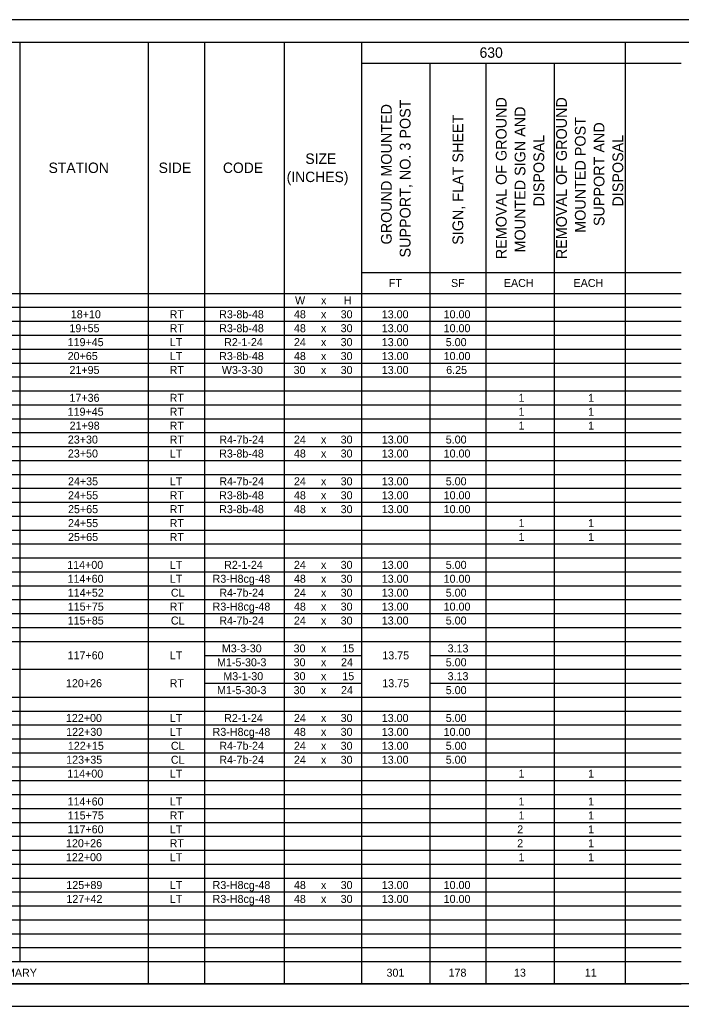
# Model space of a CAD drawing. Extents: x 10.3 to 44.3, y 3.4 to 25.4.
# Drawn here: x 18.06 to 32.81, y 3.4 to 25.4 of the extents above; entities that cross this region are included whole.
import ezdxf

# ---------------------------------------------------------------- set-up
doc = ezdxf.new("R2010")
doc.units = 0
for name, color, linetype in [('SH_Border', 7, 'Continuous'), ('SH_Cut_Line', 7, 'Continuous'), ('SH_Text', 7, 'Continuous')]:
    doc.layers.add(name, color=color, linetype=linetype)

msp = doc.modelspace()

# ---------------------------------------------------------------- linework, layer by layer
at = {"layer": 'SH_Border'}
msp.add_lwpolyline([(12.306, 24.905), (43.806, 24.905), (43.806, 3.905), (12.306, 3.905)], close=True, dxfattribs=at)
at = {"layer": 'SH_Cut_Line'}
msp.add_lwpolyline([(10.306, 3.405), (44.306, 3.405), (44.306, 25.405), (10.306, 25.405)], close=True, dxfattribs=at)
at = {"layer": 'SH_Text'}
for p, q in [((12.306, 24.905), (18.057, 24.905)), ((18.057, 24.905), (20.924, 24.905)), ((18.057, 24.905), (18.057, 19.767)), ((20.924, 24.905), (23.952, 24.905)), ((20.924, 24.905), (20.924, 19.767)), ((22.174, 24.905), (22.174, 19.767)), ((23.952, 24.905), (24.657, 24.905)), ((23.952, 24.905), (23.952, 19.767)), ((24.657, 24.905), (32.81, 24.905)), ((25.682, 24.905), (25.682, 19.767)), ((31.561, 24.905), (31.561, 19.767)), ((25.682, 24.439), (32.81, 24.439)), ((27.204, 24.439), (27.204, 19.767)), ((28.453, 24.439), (28.453, 19.767)), ((29.975, 24.439), (29.975, 19.767)), ((18.057, 19.767), (18.057, 11.851)), ((20.924, 19.767), (20.924, 11.851)), ((22.174, 19.767), (22.174, 11.851)), ((23.952, 19.767), (23.952, 11.851)), ((25.682, 19.767), (32.81, 19.767)), ((25.682, 19.767), (25.682, 11.851)), ((27.204, 19.767), (27.204, 11.851)), ((28.453, 19.767), (28.453, 11.851)), ((29.975, 19.767), (29.975, 11.851)), ((31.561, 19.767), (31.561, 11.851)), ((12.306, 19.301), (18.057, 19.301)), ((18.057, 19.301), (20.924, 19.301)), ((20.924, 19.301), (23.952, 19.301)), ((23.952, 19.301), (24.657, 19.301)), ((24.657, 19.301), (32.81, 19.301)), ((12.306, 18.991), (18.057, 18.991)), ((18.057, 18.991), (20.924, 18.991)), ((20.924, 18.991), (23.952, 18.991)), ((23.952, 18.991), (24.657, 18.991)), ((24.657, 18.991), (32.81, 18.991)), ((12.306, 18.681), (18.057, 18.681)), ((18.057, 18.681), (20.924, 18.681)), ((20.924, 18.681), (23.952, 18.681)), ((23.952, 18.681), (24.657, 18.681)), ((24.657, 18.681), (32.81, 18.681)), ((12.306, 18.37), (18.057, 18.37)), ((18.057, 18.37), (20.924, 18.37)), ((20.924, 18.37), (23.952, 18.37)), ((23.952, 18.37), (24.657, 18.37)), ((24.657, 18.37), (32.81, 18.37)), ((12.306, 18.06), (18.057, 18.06)), ((18.057, 18.06), (20.924, 18.06)), ((20.924, 18.06), (23.952, 18.06)), ((23.952, 18.06), (24.657, 18.06)), ((24.657, 18.06), (32.81, 18.06)), ((12.306, 17.749), (18.057, 17.749)), ((18.057, 17.749), (20.924, 17.749)), ((20.924, 17.749), (23.952, 17.749)), ((23.952, 17.749), (24.657, 17.749)), ((24.657, 17.749), (32.81, 17.749)), ((12.306, 17.439), (18.057, 17.439)), ((18.057, 17.439), (20.924, 17.439)), ((20.924, 17.439), (23.952, 17.439)), ((23.952, 17.439), (24.657, 17.439)), ((24.657, 17.439), (32.81, 17.439)), ((12.306, 17.128), (18.057, 17.128)), ((18.057, 17.128), (20.924, 17.128)), ((20.924, 17.128), (23.952, 17.128)), ((23.952, 17.128), (24.657, 17.128)), ((24.657, 17.128), (32.81, 17.128)), ((12.306, 16.818), (18.057, 16.818)), ((18.057, 16.818), (20.924, 16.818)), ((20.924, 16.818), (23.952, 16.818)), ((23.952, 16.818), (24.657, 16.818)), ((24.657, 16.818), (32.81, 16.818)), ((12.306, 16.508), (18.057, 16.508)), ((18.057, 16.508), (20.924, 16.508)), ((20.924, 16.508), (23.952, 16.508)), ((23.952, 16.508), (24.657, 16.508)), ((24.657, 16.508), (32.81, 16.508)), ((12.306, 16.197), (18.057, 16.197)), ((18.057, 16.197), (20.924, 16.197)), ((20.924, 16.197), (23.952, 16.197)), ((23.952, 16.197), (24.657, 16.197)), ((24.657, 16.197), (32.81, 16.197)), ((12.306, 15.887), (18.057, 15.887)), ((18.057, 15.887), (20.924, 15.887)), ((20.924, 15.887), (23.952, 15.887)), ((23.952, 15.887), (24.657, 15.887)), ((24.657, 15.887), (32.81, 15.887)), ((12.306, 15.576), (18.057, 15.576)), ((18.057, 15.576), (20.924, 15.576)), ((20.924, 15.576), (23.952, 15.576)), ((23.952, 15.576), (24.657, 15.576)), ((24.657, 15.576), (32.81, 15.576)), ((12.306, 15.266), (18.057, 15.266)), ((18.057, 15.266), (20.924, 15.266)), ((20.924, 15.266), (23.952, 15.266)), ((23.952, 15.266), (24.657, 15.266)), ((24.657, 15.266), (32.81, 15.266)), ((12.306, 14.956), (18.057, 14.956)), ((18.057, 14.956), (20.924, 14.956)), ((20.924, 14.956), (23.952, 14.956)), ((23.952, 14.956), (24.657, 14.956)), ((24.657, 14.956), (32.81, 14.956)), ((12.306, 14.645), (18.057, 14.645)), ((18.057, 14.645), (20.924, 14.645)), ((20.924, 14.645), (23.952, 14.645)), ((23.952, 14.645), (24.657, 14.645)), ((24.657, 14.645), (32.81, 14.645)), ((12.306, 14.335), (18.057, 14.335)), ((18.057, 14.335), (20.924, 14.335)), ((20.924, 14.335), (23.952, 14.335)), ((23.952, 14.335), (24.657, 14.335)), ((24.657, 14.335), (32.81, 14.335)), ((12.306, 14.024), (18.057, 14.024)), ((18.057, 14.024), (20.924, 14.024)), ((20.924, 14.024), (23.952, 14.024)), ((23.952, 14.024), (24.657, 14.024)), ((24.657, 14.024), (32.81, 14.024)), ((12.306, 13.714), (18.057, 13.714)), ((18.057, 13.714), (20.924, 13.714)), ((20.924, 13.714), (23.952, 13.714)), ((23.952, 13.714), (24.657, 13.714)), ((24.657, 13.714), (32.81, 13.714)), ((12.306, 13.403), (18.057, 13.403)), ((18.057, 13.403), (20.924, 13.403)), ((20.924, 13.403), (23.952, 13.403)), ((23.952, 13.403), (24.657, 13.403)), ((24.657, 13.403), (32.81, 13.403)), ((12.306, 13.093), (18.057, 13.093)), ((18.057, 13.093), (20.924, 13.093)), ((20.924, 13.093), (23.952, 13.093)), ((23.952, 13.093), (24.657, 13.093)), ((24.657, 13.093), (32.81, 13.093)), ((12.306, 12.783), (18.057, 12.783)), ((18.057, 12.783), (20.924, 12.783)), ((20.924, 12.783), (23.952, 12.783)), ((23.952, 12.783), (24.657, 12.783)), ((24.657, 12.783), (32.81, 12.783)), ((12.306, 12.472), (18.057, 12.472)), ((18.057, 12.472), (20.924, 12.472)), ((20.924, 12.472), (23.952, 12.472)), ((23.952, 12.472), (24.657, 12.472)), ((24.657, 12.472), (32.81, 12.472)), ((12.306, 12.162), (18.057, 12.162)), ((18.057, 12.162), (20.924, 12.162)), ((20.924, 12.162), (23.952, 12.162)), ((23.952, 12.162), (24.657, 12.162)), ((24.657, 12.162), (32.81, 12.162)), ((12.306, 11.851), (18.057, 11.851)), ((18.057, 11.851), (20.924, 11.851)), ((18.057, 11.851), (18.057, 4.401)), ((20.924, 11.851), (23.952, 11.851)), ((20.924, 11.851), (20.924, 3.905)), ((22.174, 11.851), (22.174, 3.905)), ((23.952, 11.851), (24.657, 11.851)), ((23.952, 11.851), (23.952, 3.905)), ((24.657, 11.851), (32.81, 11.851)), ((25.682, 11.851), (25.682, 3.905)), ((27.204, 11.851), (27.204, 3.905)), ((28.453, 11.851), (28.453, 3.905)), ((29.975, 11.851), (29.975, 3.905)), ((31.561, 11.851), (31.561, 3.905)), ((12.306, 11.541), (18.057, 11.541)), ((18.057, 11.541), (20.924, 11.541)), ((20.924, 11.541), (23.952, 11.541)), ((23.952, 11.541), (24.657, 11.541)), ((24.657, 11.541), (32.81, 11.541)), ((22.174, 11.23), (23.952, 11.23)), ((23.952, 11.23), (24.657, 11.23)), ((24.657, 11.23), (25.682, 11.23)), ((27.204, 11.23), (32.81, 11.23)), ((12.306, 10.92), (18.057, 10.92)), ((18.057, 10.92), (20.924, 10.92)), ((20.924, 10.92), (23.952, 10.92)), ((23.952, 10.92), (24.657, 10.92)), ((24.657, 10.92), (32.81, 10.92)), ((22.174, 10.61), (23.952, 10.61)), ((23.952, 10.61), (24.657, 10.61)), ((24.657, 10.61), (25.682, 10.61)), ((27.204, 10.61), (32.81, 10.61)), ((12.306, 10.299), (18.057, 10.299)), ((18.057, 10.299), (20.924, 10.299)), ((20.924, 10.299), (23.952, 10.299)), ((23.952, 10.299), (24.657, 10.299)), ((24.657, 10.299), (32.81, 10.299)), ((12.306, 9.989), (18.057, 9.989)), ((18.057, 9.989), (20.924, 9.989)), ((20.924, 9.989), (23.952, 9.989)), ((23.952, 9.989), (24.657, 9.989)), ((24.657, 9.989), (32.81, 9.989)), ((12.306, 9.678), (18.057, 9.678)), ((18.057, 9.678), (20.924, 9.678)), ((20.924, 9.678), (23.952, 9.678)), ((23.952, 9.678), (24.657, 9.678)), ((24.657, 9.678), (32.81, 9.678)), ((12.306, 9.368), (18.057, 9.368)), ((18.057, 9.368), (20.924, 9.368)), ((20.924, 9.368), (23.952, 9.368)), ((23.952, 9.368), (24.657, 9.368)), ((24.657, 9.368), (32.81, 9.368)), ((12.306, 9.058), (18.057, 9.058)), ((18.057, 9.058), (20.924, 9.058)), ((20.924, 9.058), (23.952, 9.058)), ((23.952, 9.058), (24.657, 9.058)), ((24.657, 9.058), (32.81, 9.058)), ((12.306, 8.747), (18.057, 8.747)), ((18.057, 8.747), (20.924, 8.747)), ((20.924, 8.747), (23.952, 8.747)), ((23.952, 8.747), (24.657, 8.747)), ((24.657, 8.747), (32.81, 8.747)), ((12.306, 8.437), (18.057, 8.437)), ((18.057, 8.437), (20.924, 8.437)), ((20.924, 8.437), (23.952, 8.437)), ((23.952, 8.437), (24.657, 8.437)), ((24.657, 8.437), (32.81, 8.437)), ((12.306, 8.126), (18.057, 8.126)), ((18.057, 8.126), (20.924, 8.126)), ((20.924, 8.126), (23.952, 8.126)), ((23.952, 8.126), (24.657, 8.126)), ((24.657, 8.126), (32.81, 8.126)), ((12.306, 7.816), (18.057, 7.816)), ((18.057, 7.816), (20.924, 7.816)), ((20.924, 7.816), (23.952, 7.816)), ((23.952, 7.816), (24.657, 7.816)), ((24.657, 7.816), (32.81, 7.816)), ((12.306, 7.505), (18.057, 7.505)), ((18.057, 7.505), (20.924, 7.505)), ((20.924, 7.505), (23.952, 7.505)), ((23.952, 7.505), (24.657, 7.505)), ((24.657, 7.505), (32.81, 7.505)), ((12.306, 7.195), (18.057, 7.195)), ((18.057, 7.195), (20.924, 7.195)), ((20.924, 7.195), (23.952, 7.195)), ((23.952, 7.195), (24.657, 7.195)), ((24.657, 7.195), (32.81, 7.195)), ((12.306, 6.885), (18.057, 6.885)), ((18.057, 6.885), (20.924, 6.885)), ((20.924, 6.885), (23.952, 6.885)), ((23.952, 6.885), (24.657, 6.885)), ((24.657, 6.885), (32.81, 6.885)), ((12.306, 6.574), (18.057, 6.574)), ((18.057, 6.574), (20.924, 6.574)), ((20.924, 6.574), (23.952, 6.574)), ((23.952, 6.574), (24.657, 6.574)), ((24.657, 6.574), (32.81, 6.574)), ((12.306, 6.264), (18.057, 6.264)), ((18.057, 6.264), (20.924, 6.264)), ((20.924, 6.264), (23.952, 6.264)), ((23.952, 6.264), (24.657, 6.264)), ((24.657, 6.264), (32.81, 6.264)), ((12.306, 5.953), (18.057, 5.953)), ((18.057, 5.953), (20.924, 5.953)), ((20.924, 5.953), (23.952, 5.953)), ((23.952, 5.953), (24.657, 5.953)), ((24.657, 5.953), (32.81, 5.953)), ((12.306, 5.643), (18.057, 5.643)), ((18.057, 5.643), (20.924, 5.643)), ((20.924, 5.643), (23.952, 5.643)), ((23.952, 5.643), (24.657, 5.643)), ((24.657, 5.643), (32.81, 5.643)), ((12.306, 5.332), (18.057, 5.332)), ((18.057, 5.332), (20.924, 5.332)), ((20.924, 5.332), (23.952, 5.332)), ((23.952, 5.332), (24.657, 5.332)), ((24.657, 5.332), (32.81, 5.332)), ((12.306, 5.022), (18.057, 5.022)), ((18.057, 5.022), (20.924, 5.022)), ((20.924, 5.022), (23.952, 5.022)), ((23.952, 5.022), (24.657, 5.022)), ((24.657, 5.022), (32.81, 5.022)), ((12.306, 4.712), (18.057, 4.712)), ((18.057, 4.712), (20.924, 4.712)), ((20.924, 4.712), (23.952, 4.712)), ((23.952, 4.712), (24.657, 4.712)), ((24.657, 4.712), (32.81, 4.712)), ((12.306, 4.401), (18.057, 4.401)), ((18.057, 4.401), (20.924, 4.401)), ((20.924, 4.401), (23.952, 4.401)), ((23.952, 4.401), (24.657, 4.401)), ((24.657, 4.401), (32.81, 4.401)), ((12.306, 3.905), (18.057, 3.905)), ((18.057, 3.905), (20.924, 3.905)), ((20.924, 3.905), (23.952, 3.905)), ((23.952, 3.905), (24.657, 3.905)), ((24.657, 3.905), (32.81, 3.905))]:
    msp.add_line(p, q, dxfattribs=at)

# ---------------------------------------------------------------- texts
for s, height, p in [('630', 0.232, (28.312, 24.556)), ('STATION', 0.232, (18.7, 21.987)), ('SIDE', 0.232, (21.155, 21.987)), ('CODE', 0.232, (22.588, 21.987)), ('SIZE', 0.232, (24.427, 22.19)), ('(INCHES)', 0.232, (24.009, 21.784)), ('FT', 0.1785, (26.287, 19.445)), ('SF', 0.1785, (27.675, 19.445)), ('EACH', 0.1785, (28.854, 19.445)), ('EACH', 0.1785, (30.408, 19.445)), ('W', 0.178, (24.197, 19.057)), ('x', 0.178, (24.777, 19.057)), ('H', 0.178, (25.286, 19.057)), ('18+10', 0.1785, (19.196, 18.747)), ('RT', 0.1785, (21.4, 18.747)), ('R3-8b-48', 0.1785, (22.505, 18.747)), ('48', 0.1785, (24.172, 18.747)), ('30', 0.1785, (25.214, 18.747)), ('13.00', 0.1785, (26.131, 18.747)), ('10.00', 0.1785, (27.511, 18.747)), ('x', 0.178, (24.775, 18.747)), ('19+55', 0.1785, (19.165, 18.436)), ('RT', 0.1785, (21.4, 18.436)), ('R3-8b-48', 0.1785, (22.505, 18.436)), ('48', 0.1785, (24.172, 18.436)), ('x', 0.178, (24.775, 18.436)), ('30', 0.1785, (25.214, 18.436)), ('13.00', 0.1785, (26.131, 18.436)), ('10.00', 0.1785, (27.511, 18.436)), ('119+45', 0.1785, (19.125, 18.126)), ('LT', 0.1785, (21.404, 18.126)), ('R2-1-24', 0.1785, (22.616, 18.126)), ('24', 0.1785, (24.172, 18.126)), ('x', 0.178, (24.775, 18.126)), ('30', 0.1785, (25.214, 18.126)), ('13.00', 0.1785, (26.131, 18.126)), ('5.00', 0.1785, (27.558, 18.126)), ('20+65', 0.1785, (19.126, 17.815)), ('LT', 0.1785, (21.404, 17.815)), ('R3-8b-48', 0.1785, (22.505, 17.815)), ('48', 0.1785, (24.172, 17.815)), ('x', 0.178, (24.775, 17.815)), ('30', 0.1785, (25.214, 17.815)), ('13.00', 0.1785, (26.131, 17.815)), ('10.00', 0.1785, (27.511, 17.815)), ('21+95', 0.1785, (19.166, 17.505)), ('RT', 0.1785, (21.4, 17.505)), ('W3-3-30', 0.1785, (22.564, 17.505)), ('30', 0.1785, (24.165, 17.505)), ('x', 0.178, (24.775, 17.505)), ('30', 0.1785, (25.214, 17.505)), ('13.00', 0.1785, (26.131, 17.505)), ('6.25', 0.1785, (27.568, 17.505)), ('17+36', 0.1785, (19.166, 16.884)), ('RT', 0.1785, (21.4, 16.884)), ('1', 0.178, (29.18, 16.884)), ('1', 0.178, (30.733, 16.884)), ('119+45', 0.1785, (19.125, 16.574)), ('RT', 0.1785, (21.4, 16.574)), ('1', 0.178, (29.18, 16.574)), ('1', 0.178, (30.733, 16.574)), ('21+98', 0.1785, (19.169, 16.263)), ('RT', 0.1785, (21.4, 16.263)), ('1', 0.178, (29.18, 16.263)), ('1', 0.178, (30.733, 16.263)), ('23+30', 0.1785, (19.13, 15.953)), ('RT', 0.1785, (21.4, 15.953)), ('R4-7b-24', 0.1785, (22.508, 15.953)), ('24', 0.1785, (24.172, 15.953)), ('x', 0.178, (24.775, 15.953)), ('30', 0.1785, (25.214, 15.953)), ('13.00', 0.1785, (26.131, 15.953)), ('5.00', 0.1785, (27.558, 15.953)), ('23+50', 0.1785, (19.131, 15.642)), ('LT', 0.1785, (21.404, 15.642)), ('R3-8b-48', 0.1785, (22.505, 15.642)), ('48', 0.1785, (24.172, 15.642)), ('x', 0.178, (24.775, 15.642)), ('30', 0.1785, (25.214, 15.642)), ('13.00', 0.1785, (26.131, 15.642)), ('10.00', 0.1785, (27.511, 15.642)), ('24+35', 0.1785, (19.133, 15.022)), ('LT', 0.1785, (21.404, 15.022)), ('R4-7b-24', 0.1785, (22.508, 15.022)), ('24', 0.1785, (24.172, 15.022)), ('30', 0.1785, (25.214, 15.022)), ('13.00', 0.1785, (26.131, 15.022)), ('5.00', 0.1785, (27.558, 15.022)), ('x', 0.178, (24.775, 15.022)), ('24+55', 0.1785, (19.134, 14.711)), ('RT', 0.1785, (21.4, 14.711)), ('R3-8b-48', 0.1785, (22.505, 14.711)), ('48', 0.1785, (24.172, 14.711)), ('x', 0.178, (24.775, 14.711)), ('30', 0.1785, (25.214, 14.711)), ('13.00', 0.1785, (26.131, 14.711)), ('10.00', 0.1785, (27.511, 14.711)), ('25+65', 0.1785, (19.134, 14.401)), ('RT', 0.1785, (21.4, 14.401)), ('R3-8b-48', 0.1785, (22.505, 14.401)), ('48', 0.1785, (24.172, 14.401)), ('x', 0.178, (24.775, 14.401)), ('30', 0.1785, (25.214, 14.401)), ('13.00', 0.1785, (26.131, 14.401)), ('10.00', 0.1785, (27.511, 14.401)), ('24+55', 0.1785, (19.134, 14.09)), ('RT', 0.1785, (21.4, 14.09)), ('1', 0.178, (29.18, 14.09)), ('1', 0.178, (30.733, 14.09)), ('25+65', 0.1785, (19.134, 13.78)), ('RT', 0.1785, (21.4, 13.78)), ('1', 0.178, (29.18, 13.78)), ('1', 0.178, (30.733, 13.78)), ('114+00', 0.1785, (19.116, 13.159)), ('LT', 0.1785, (21.404, 13.159)), ('R2-1-24', 0.1785, (22.616, 13.159)), ('24', 0.1785, (24.172, 13.159)), ('x', 0.178, (24.775, 13.159)), ('30', 0.1785, (25.214, 13.159)), ('13.00', 0.1785, (26.131, 13.159)), ('5.00', 0.1785, (27.558, 13.159)), ('114+60', 0.1785, (19.123, 12.849)), ('LT', 0.1785, (21.404, 12.849)), ('R3-H8cg-48', 0.1785, (22.358, 12.849)), ('48', 0.1785, (24.172, 12.849)), ('x', 0.178, (24.775, 12.849)), ('30', 0.1785, (25.214, 12.849)), ('13.00', 0.1785, (26.131, 12.849)), ('10.00', 0.1785, (27.511, 12.849)), ('114+52', 0.1785, (19.128, 12.538)), ('CL', 0.1785, (21.428, 12.538)), ('R4-7b-24', 0.1785, (22.508, 12.538)), ('24', 0.1785, (24.172, 12.538)), ('x', 0.178, (24.775, 12.538)), ('30', 0.1785, (25.214, 12.538)), ('13.00', 0.1785, (26.131, 12.538)), ('5.00', 0.1785, (27.558, 12.538)), ('115+75', 0.1785, (19.128, 12.228)), ('RT', 0.1785, (21.4, 12.228)), ('R3-H8cg-48', 0.1785, (22.358, 12.228)), ('48', 0.1785, (24.172, 12.228)), ('x', 0.178, (24.775, 12.228)), ('30', 0.1785, (25.214, 12.228)), ('13.00', 0.1785, (26.131, 12.228)), ('10.00', 0.1785, (27.511, 12.228)), ('R4-7b-24', 0.1785, (22.508, 11.917)), ('115+85', 0.1785, (19.127, 11.917)), ('CL', 0.1785, (21.428, 11.917)), ('24', 0.1785, (24.172, 11.917)), ('x', 0.178, (24.775, 11.917)), ('30', 0.1785, (25.214, 11.917)), ('13.00', 0.1785, (26.131, 11.917)), ('5.00', 0.1785, (27.558, 11.917)), ('M3-3-30', 0.1785, (22.564, 11.296)), ('30', 0.1785, (24.165, 11.296)), ('15', 0.1785, (25.251, 11.296)), ('3.13', 0.1785, (27.599, 11.296)), ('117+60', 0.1785, (19.124, 11.141)), ('LT', 0.1785, (21.404, 11.141)), ('x', 0.178, (24.775, 11.296)), ('13.75', 0.1785, (26.143, 11.141)), ('M1-5-30-3', 0.1785, (22.457, 10.986)), ('30', 0.1785, (24.165, 10.986)), ('x', 0.178, (24.775, 10.986)), ('24', 0.1785, (25.222, 10.986)), ('5.00', 0.1785, (27.558, 10.986)), ('M3-1-30', 0.1785, (22.598, 10.676)), ('30', 0.1785, (24.165, 10.676)), ('x', 0.178, (24.775, 10.676)), ('15', 0.1785, (25.251, 10.676)), ('3.13', 0.1785, (27.599, 10.676)), ('120+26', 0.1785, (19.089, 10.52)), ('RT', 0.1785, (21.4, 10.52)), ('13.75', 0.1785, (26.143, 10.52)), ('M1-5-30-3', 0.1785, (22.457, 10.365)), ('30', 0.1785, (24.165, 10.365)), ('x', 0.178, (24.775, 10.365)), ('24', 0.1785, (25.222, 10.365)), ('5.00', 0.1785, (27.558, 10.365)), ('122+00', 0.1785, (19.087, 9.744)), ('LT', 0.1785, (21.404, 9.744)), ('R2-1-24', 0.1785, (22.616, 9.744)), ('24', 0.1785, (24.172, 9.744)), ('30', 0.1785, (25.214, 9.744)), ('13.00', 0.1785, (26.131, 9.744)), ('5.00', 0.1785, (27.558, 9.744)), ('x', 0.178, (24.775, 9.744)), ('122+30', 0.1785, (19.093, 9.434)), ('LT', 0.1785, (21.404, 9.434)), ('R3-H8cg-48', 0.1785, (22.358, 9.434)), ('48', 0.1785, (24.172, 9.434)), ('x', 0.178, (24.775, 9.434)), ('30', 0.1785, (25.214, 9.434)), ('13.00', 0.1785, (26.131, 9.434)), ('10.00', 0.1785, (27.511, 9.434)), ('122+15', 0.1785, (19.13, 9.124)), ('CL', 0.1785, (21.428, 9.124)), ('R4-7b-24', 0.1785, (22.508, 9.124)), ('24', 0.1785, (24.172, 9.124)), ('x', 0.178, (24.775, 9.124)), ('30', 0.1785, (25.214, 9.124)), ('13.00', 0.1785, (26.131, 9.124)), ('5.00', 0.1785, (27.558, 9.124)), ('123+35', 0.1785, (19.093, 8.813)), ('CL', 0.1785, (21.428, 8.813)), ('R4-7b-24', 0.1785, (22.508, 8.813)), ('24', 0.1785, (24.172, 8.813)), ('x', 0.178, (24.775, 8.813)), ('30', 0.1785, (25.214, 8.813)), ('13.00', 0.1785, (26.131, 8.813)), ('5.00', 0.1785, (27.558, 8.813)), ('114+00', 0.1785, (19.116, 8.503)), ('LT', 0.1785, (21.404, 8.503)), ('1', 0.178, (29.18, 8.503)), ('1', 0.178, (30.733, 8.503)), ('114+60', 0.1785, (19.123, 7.882)), ('LT', 0.1785, (21.404, 7.882)), ('1', 0.178, (29.18, 7.882)), ('1', 0.178, (30.733, 7.882)), ('115+75', 0.1785, (19.128, 7.571)), ('RT', 0.1785, (21.4, 7.571)), ('1', 0.178, (29.18, 7.571)), ('1', 0.178, (30.733, 7.571)), ('117+60', 0.1785, (19.124, 7.261)), ('LT', 0.1785, (21.404, 7.261)), ('2', 0.178, (29.152, 7.261)), ('1', 0.178, (30.733, 7.261)), ('120+26', 0.1785, (19.089, 6.951)), ('RT', 0.1785, (21.4, 6.951)), ('2', 0.178, (29.152, 6.951)), ('1', 0.178, (30.733, 6.951)), ('122+00', 0.1785, (19.087, 6.64)), ('LT', 0.1785, (21.404, 6.64)), ('1', 0.178, (29.18, 6.64)), ('1', 0.178, (30.733, 6.64)), ('125+89', 0.1785, (19.096, 6.019)), ('LT', 0.1785, (21.404, 6.019)), ('R3-H8cg-48', 0.1785, (22.358, 6.019)), ('48', 0.1785, (24.172, 6.019)), ('30', 0.1785, (25.214, 6.019)), ('13.00', 0.1785, (26.131, 6.019)), ('10.00', 0.1785, (27.511, 6.019)), ('x', 0.178, (24.775, 6.019)), ('127+42', 0.1785, (19.098, 5.709)), ('LT', 0.1785, (21.404, 5.709)), ('R3-H8cg-48', 0.1785, (22.358, 5.709)), ('48', 0.1785, (24.172, 5.709)), ('x', 0.178, (24.775, 5.709)), ('30', 0.1785, (25.214, 5.709)), ('13.00', 0.1785, (26.131, 5.709)), ('10.00', 0.1785, (27.511, 5.709)), ('TOTALS CARRIED TO GENERAL SUMMARY', 0.17849, (13.48, 4.064)), ('301', 0.1785, (26.237, 4.064)), ('178', 0.1785, (27.621, 4.064)), ('13', 0.1785, (29.08, 4.064)), ('11', 0.1785, (30.659, 4.064))]:
    msp.add_text(s, height=height, dxfattribs=at).set_placement(p)
for s, height, p in [('SUPPORT, NO. 3 POST', 0.23948, (26.772, 20.102)), ('REMOVAL OF GROUND', 0.23948, (28.915, 20.065)), ('REMOVAL OF GROUND', 0.23948, (30.259, 20.065)), ('GROUND MOUNTED', 0.23948, (26.353, 20.393)), ('MOUNTED SIGN AND', 0.23948, (29.334, 20.214)), ('SIGN, FLAT SHEET', 0.23948, (27.948, 20.386)), ('MOUNTED POST', 0.23948, (30.678, 20.654)), ('SUPPORT AND', 0.23948, (31.097, 20.804)), ('DISPOSAL', 0.2395, (29.753, 21.237)), ('DISPOSAL', 0.2395, (31.516, 21.237))]:
    msp.add_text(s, height=height, rotation=90, dxfattribs=at).set_placement(p)

doc.saveas('drawing.dxf')
